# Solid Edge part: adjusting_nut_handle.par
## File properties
Title: Adjusting nut handle
Author: Deepak Maini
Template: Normal.par
Last saved by: CADCIM
Revision: 5
Application: Solid Edge
Accuracy: 0.99
Material: aluminum
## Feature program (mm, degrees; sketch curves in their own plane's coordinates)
sketch for "unnamed Protrusion 1" plane through (0, 0, 0) normal (0, -1, 0) x-axis (1, 0, 0)
  circle centre (0, 0) radius 9.5123
extrude "unnamed Protrusion 1" add finite 127 symmetric
chamfer "Chamfer_1" setback 1.5748
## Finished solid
Body 1: solid body, 5 faces, 4 edges, 0 vertices.
  Faces by surface: cone 2, plane 2, cylinder 1
  Edges by curve: circle 4
Bounding box of the edges (mm): 19.025 x 127.000 x 19.025, from (-9.5123, -63.5, -9.5123) to (9.5123, 63.5, 9.5123).
Cylindrical faces by radius (mm): R9.5123 x1
Conical faces (half-angle, radius in mm at the cone's reference point): 45 deg R7.9375 x1, 45 deg R9.5123 x1
Planar faces by outward normal: +y 1, -y 1
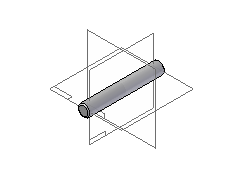
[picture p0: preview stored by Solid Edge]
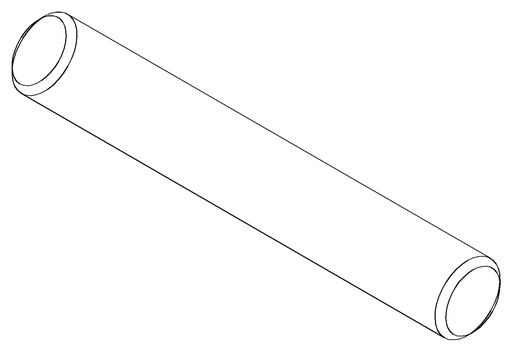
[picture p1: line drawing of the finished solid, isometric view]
